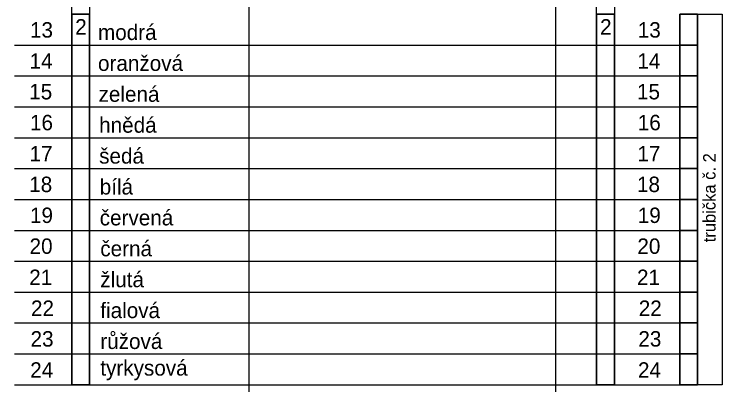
# Model space of a CAD drawing. Extents: x 1901 to 2519, y -3585 to -3154.
# Drawn here: x 2032.8 to 2113, y -3287.5 to -3245.2 of the extents above; entities that cross this region are included whole.
import ezdxf

# ---------------------------------------------------------------- set-up
doc = ezdxf.new("R2010")
doc.units = 0
doc.layers.add('rozvláknění', color=7, linetype='Continuous')

msp = doc.modelspace()

# ---------------------------------------------------------------- linework, layer by layer
at = {"layer": 'rozvláknění'}
for p, q in [((2032.823, -3248.764), (2108.565, -3248.767)), ((2032.823, -3252.283), (2108.565, -3252.285)), ((2032.823, -3255.801), (2108.565, -3255.803)), ((2032.823, -3259.319), (2108.565, -3259.321)), ((2032.823, -3262.837), (2108.565, -3262.839)), ((2032.823, -3266.355), (2108.565, -3266.357)), ((2032.823, -3269.874), (2108.565, -3269.876)), ((2032.823, -3273.392), (2108.565, -3273.394)), ((2032.823, -3276.91), (2108.565, -3276.912)), ((2032.823, -3280.428), (2108.565, -3280.43)), ((2032.823, -3283.946), (2108.565, -3283.948)), ((2032.823, -3287.465), (2108.565, -3287.467))]:
    msp.add_line(p, q, dxfattribs=at)
for points in [[(2014.869, -3178.545), (2059.522, -3178.544), (2059.522, -3570.656), (2014.869, -3570.656)], [(2094.462, -3178.545), (2128.46, -3178.544), (2128.46, -3571.465), (2094.462, -3571.465)], [(2041.391, -3287.481), (2039.35, -3287.481), (2039.35, -3203.008), (2041.391, -3203.008)], [(2101.143, -3287.481), (2099.102, -3287.481), (2099.102, -3203.008), (2101.143, -3203.008)], [(2041.391, -3287.467), (2039.35, -3287.467), (2039.35, -3245.248), (2041.391, -3245.248)], [(2101.143, -3287.467), (2099.102, -3287.467), (2099.102, -3245.248), (2101.143, -3245.248)], [(2108.565, -3245.248), (2110.606, -3245.248), (2110.606, -3248.767), (2108.565, -3248.767)], [(2108.565, -3245.248), (2110.606, -3245.248), (2110.606, -3248.767), (2108.565, -3248.767)], [(2110.606, -3245.248), (2113.393, -3245.248), (2113.393, -3287.463), (2110.606, -3287.463)], [(2108.565, -3248.767), (2110.606, -3248.767), (2110.606, -3252.285), (2108.565, -3252.285)], [(2108.565, -3248.767), (2110.606, -3248.767), (2110.606, -3252.285), (2108.565, -3252.285)], [(2108.565, -3252.285), (2110.606, -3252.285), (2110.606, -3255.803), (2108.565, -3255.803)], [(2108.565, -3252.285), (2110.606, -3252.285), (2110.606, -3255.803), (2108.565, -3255.803)], [(2108.565, -3255.803), (2110.606, -3255.803), (2110.606, -3259.321), (2108.565, -3259.321)], [(2108.565, -3255.803), (2110.606, -3255.803), (2110.606, -3259.321), (2108.565, -3259.321)], [(2108.565, -3259.321), (2110.606, -3259.321), (2110.606, -3262.839), (2108.565, -3262.839)], [(2108.565, -3259.321), (2110.606, -3259.321), (2110.606, -3262.839), (2108.565, -3262.839)], [(2108.565, -3262.839), (2110.606, -3262.839), (2110.606, -3266.357), (2108.565, -3266.357)], [(2108.565, -3262.839), (2110.606, -3262.839), (2110.606, -3266.357), (2108.565, -3266.357)], [(2108.565, -3266.357), (2110.606, -3266.357), (2110.606, -3269.876), (2108.565, -3269.876)], [(2108.565, -3266.357), (2110.606, -3266.357), (2110.606, -3269.876), (2108.565, -3269.876)], [(2108.565, -3269.876), (2110.606, -3269.876), (2110.606, -3273.394), (2108.565, -3273.394)], [(2108.565, -3269.876), (2110.606, -3269.876), (2110.606, -3273.394), (2108.565, -3273.394)], [(2108.565, -3273.394), (2110.606, -3273.394), (2110.606, -3276.912), (2108.565, -3276.912)], [(2108.565, -3273.394), (2110.606, -3273.394), (2110.606, -3276.912), (2108.565, -3276.912)], [(2108.565, -3276.912), (2110.606, -3276.912), (2110.606, -3280.43), (2108.565, -3280.43)], [(2108.565, -3276.912), (2110.606, -3276.912), (2110.606, -3280.43), (2108.565, -3280.43)], [(2108.565, -3280.43), (2110.606, -3280.43), (2110.606, -3283.948), (2108.565, -3283.948)], [(2108.565, -3280.43), (2110.606, -3280.43), (2110.606, -3283.948), (2108.565, -3283.948)], [(2108.565, -3283.948), (2110.606, -3283.948), (2110.606, -3287.467), (2108.565, -3287.467)], [(2108.565, -3283.948), (2110.606, -3283.948), (2110.606, -3287.467), (2108.565, -3287.467)]]:
    msp.add_lwpolyline(points, close=True, dxfattribs=at)
for points in [[(2041.391, -3245.248), (2039.35, -3245.248), (2039.35, -3287.467), (2041.391, -3287.467), (2041.391, -3245.248)], [(2041.391, -3245.248), (2039.35, -3245.248), (2039.35, -3287.467), (2041.391, -3287.467), (2041.391, -3245.248)], [(2041.391, -3245.248), (2039.35, -3245.248), (2039.35, -3287.467), (2041.391, -3287.467), (2041.391, -3245.248)], [(2041.391, -3245.248), (2039.35, -3245.248), (2039.35, -3287.467), (2041.391, -3287.467), (2041.391, -3245.248)], [(2041.391, -3245.248), (2039.35, -3245.248), (2039.35, -3287.467), (2041.391, -3287.467), (2041.391, -3245.248)], [(2041.391, -3245.248), (2039.35, -3245.248), (2039.35, -3287.467), (2041.391, -3287.467), (2041.391, -3245.248)], [(2101.143, -3245.248), (2099.102, -3245.248), (2099.102, -3287.467), (2101.143, -3287.467), (2101.143, -3245.248)], [(2101.143, -3245.248), (2099.102, -3245.248), (2099.102, -3287.467), (2101.143, -3287.467), (2101.143, -3245.248)], [(2101.143, -3245.248), (2099.102, -3245.248), (2099.102, -3287.467), (2101.143, -3287.467), (2101.143, -3245.248)], [(2101.143, -3245.248), (2099.102, -3245.248), (2099.102, -3287.467), (2101.143, -3287.467), (2101.143, -3245.248)], [(2101.143, -3245.248), (2099.102, -3245.248), (2099.102, -3287.467), (2101.143, -3287.467), (2101.143, -3245.248)], [(2101.143, -3245.248), (2099.102, -3245.248), (2099.102, -3287.467), (2101.143, -3287.467), (2101.143, -3245.248)], [(2108.565, -3248.767), (2110.606, -3248.767), (2110.606, -3245.248), (2108.565, -3245.248), (2108.565, -3248.767)], [(2108.565, -3248.767), (2110.606, -3248.767), (2110.606, -3245.248), (2108.565, -3245.248), (2108.565, -3248.767)], [(2108.565, -3248.767), (2110.606, -3248.767), (2110.606, -3245.248), (2108.565, -3245.248), (2108.565, -3248.767)], [(2108.565, -3248.767), (2110.606, -3248.767), (2110.606, -3245.248), (2108.565, -3245.248), (2108.565, -3248.767)], [(2108.565, -3248.767), (2110.606, -3248.767), (2110.606, -3245.248), (2108.565, -3245.248), (2108.565, -3248.767)], [(2108.565, -3248.767), (2110.606, -3248.767), (2110.606, -3245.248), (2108.565, -3245.248), (2108.565, -3248.767)], [(2108.565, -3248.767), (2110.606, -3248.767), (2110.606, -3245.248), (2108.565, -3245.248), (2108.565, -3248.767)], [(2108.565, -3248.767), (2110.606, -3248.767), (2110.606, -3245.248), (2108.565, -3245.248), (2108.565, -3248.767)], [(2108.565, -3248.767), (2110.606, -3248.767), (2110.606, -3245.248), (2108.565, -3245.248), (2108.565, -3248.767)], [(2108.565, -3248.767), (2110.606, -3248.767), (2110.606, -3245.248), (2108.565, -3245.248), (2108.565, -3248.767)], [(2108.565, -3248.764), (2108.565, -3283.964)], [(2108.565, -3252.285), (2110.606, -3252.285), (2110.606, -3248.767), (2108.565, -3248.767), (2108.565, -3252.285)], [(2108.565, -3252.285), (2110.606, -3252.285), (2110.606, -3248.767), (2108.565, -3248.767), (2108.565, -3252.285)], [(2108.565, -3252.285), (2110.606, -3252.285), (2110.606, -3248.767), (2108.565, -3248.767), (2108.565, -3252.285)], [(2108.565, -3252.285), (2110.606, -3252.285), (2110.606, -3248.767), (2108.565, -3248.767), (2108.565, -3252.285)], [(2108.565, -3252.285), (2110.606, -3252.285), (2110.606, -3248.767), (2108.565, -3248.767), (2108.565, -3252.285)], [(2108.565, -3252.285), (2110.606, -3252.285), (2110.606, -3248.767), (2108.565, -3248.767), (2108.565, -3252.285)], [(2108.565, -3252.285), (2110.606, -3252.285), (2110.606, -3248.767), (2108.565, -3248.767), (2108.565, -3252.285)], [(2108.565, -3252.285), (2110.606, -3252.285), (2110.606, -3248.767), (2108.565, -3248.767), (2108.565, -3252.285)], [(2108.565, -3252.285), (2110.606, -3252.285), (2110.606, -3248.767), (2108.565, -3248.767), (2108.565, -3252.285)], [(2108.565, -3252.285), (2110.606, -3252.285), (2110.606, -3248.767), (2108.565, -3248.767), (2108.565, -3252.285)], [(2108.565, -3255.803), (2110.606, -3255.803), (2110.606, -3252.285), (2108.565, -3252.285), (2108.565, -3255.803)], [(2108.565, -3255.803), (2110.606, -3255.803), (2110.606, -3252.285), (2108.565, -3252.285), (2108.565, -3255.803)], [(2108.565, -3255.803), (2110.606, -3255.803), (2110.606, -3252.285), (2108.565, -3252.285), (2108.565, -3255.803)], [(2108.565, -3255.803), (2110.606, -3255.803), (2110.606, -3252.285), (2108.565, -3252.285), (2108.565, -3255.803)], [(2108.565, -3255.803), (2110.606, -3255.803), (2110.606, -3252.285), (2108.565, -3252.285), (2108.565, -3255.803)], [(2108.565, -3255.803), (2110.606, -3255.803), (2110.606, -3252.285), (2108.565, -3252.285), (2108.565, -3255.803)], [(2108.565, -3255.803), (2110.606, -3255.803), (2110.606, -3252.285), (2108.565, -3252.285), (2108.565, -3255.803)], [(2108.565, -3255.803), (2110.606, -3255.803), (2110.606, -3252.285), (2108.565, -3252.285), (2108.565, -3255.803)], [(2108.565, -3255.803), (2110.606, -3255.803), (2110.606, -3252.285), (2108.565, -3252.285), (2108.565, -3255.803)], [(2108.565, -3255.803), (2110.606, -3255.803), (2110.606, -3252.285), (2108.565, -3252.285), (2108.565, -3255.803)], [(2108.565, -3259.321), (2110.606, -3259.321), (2110.606, -3255.803), (2108.565, -3255.803), (2108.565, -3259.321)], [(2108.565, -3259.321), (2110.606, -3259.321), (2110.606, -3255.803), (2108.565, -3255.803), (2108.565, -3259.321)], [(2108.565, -3259.321), (2110.606, -3259.321), (2110.606, -3255.803), (2108.565, -3255.803), (2108.565, -3259.321)], [(2108.565, -3259.321), (2110.606, -3259.321), (2110.606, -3255.803), (2108.565, -3255.803), (2108.565, -3259.321)], [(2108.565, -3259.321), (2110.606, -3259.321), (2110.606, -3255.803), (2108.565, -3255.803), (2108.565, -3259.321)], [(2108.565, -3259.321), (2110.606, -3259.321), (2110.606, -3255.803), (2108.565, -3255.803), (2108.565, -3259.321)], [(2108.565, -3259.321), (2110.606, -3259.321), (2110.606, -3255.803), (2108.565, -3255.803), (2108.565, -3259.321)], [(2108.565, -3259.321), (2110.606, -3259.321), (2110.606, -3255.803), (2108.565, -3255.803), (2108.565, -3259.321)], [(2108.565, -3259.321), (2110.606, -3259.321), (2110.606, -3255.803), (2108.565, -3255.803), (2108.565, -3259.321)], [(2108.565, -3259.321), (2110.606, -3259.321), (2110.606, -3255.803), (2108.565, -3255.803), (2108.565, -3259.321)], [(2108.565, -3262.839), (2110.606, -3262.839), (2110.606, -3259.321), (2108.565, -3259.321), (2108.565, -3262.839)], [(2108.565, -3262.839), (2110.606, -3262.839), (2110.606, -3259.321), (2108.565, -3259.321), (2108.565, -3262.839)], [(2108.565, -3262.839), (2110.606, -3262.839), (2110.606, -3259.321), (2108.565, -3259.321), (2108.565, -3262.839)], [(2108.565, -3262.839), (2110.606, -3262.839), (2110.606, -3259.321), (2108.565, -3259.321), (2108.565, -3262.839)], [(2108.565, -3262.839), (2110.606, -3262.839), (2110.606, -3259.321), (2108.565, -3259.321), (2108.565, -3262.839)], [(2108.565, -3262.839), (2110.606, -3262.839), (2110.606, -3259.321), (2108.565, -3259.321), (2108.565, -3262.839)], [(2108.565, -3262.839), (2110.606, -3262.839), (2110.606, -3259.321), (2108.565, -3259.321), (2108.565, -3262.839)], [(2108.565, -3262.839), (2110.606, -3262.839), (2110.606, -3259.321), (2108.565, -3259.321), (2108.565, -3262.839)], [(2108.565, -3262.839), (2110.606, -3262.839), (2110.606, -3259.321), (2108.565, -3259.321), (2108.565, -3262.839)], [(2108.565, -3262.839), (2110.606, -3262.839), (2110.606, -3259.321), (2108.565, -3259.321), (2108.565, -3262.839)], [(2108.565, -3266.357), (2110.606, -3266.357), (2110.606, -3262.839), (2108.565, -3262.839), (2108.565, -3266.357)], [(2108.565, -3266.357), (2110.606, -3266.357), (2110.606, -3262.839), (2108.565, -3262.839), (2108.565, -3266.357)], [(2108.565, -3266.357), (2110.606, -3266.357), (2110.606, -3262.839), (2108.565, -3262.839), (2108.565, -3266.357)], [(2108.565, -3266.357), (2110.606, -3266.357), (2110.606, -3262.839), (2108.565, -3262.839), (2108.565, -3266.357)], [(2108.565, -3266.357), (2110.606, -3266.357), (2110.606, -3262.839), (2108.565, -3262.839), (2108.565, -3266.357)], [(2108.565, -3266.357), (2110.606, -3266.357), (2110.606, -3262.839), (2108.565, -3262.839), (2108.565, -3266.357)], [(2108.565, -3266.357), (2110.606, -3266.357), (2110.606, -3262.839), (2108.565, -3262.839), (2108.565, -3266.357)], [(2108.565, -3266.357), (2110.606, -3266.357), (2110.606, -3262.839), (2108.565, -3262.839), (2108.565, -3266.357)], [(2108.565, -3266.357), (2110.606, -3266.357), (2110.606, -3262.839), (2108.565, -3262.839), (2108.565, -3266.357)], [(2108.565, -3266.357), (2110.606, -3266.357), (2110.606, -3262.839), (2108.565, -3262.839), (2108.565, -3266.357)], [(2108.565, -3269.876), (2110.606, -3269.876), (2110.606, -3266.357), (2108.565, -3266.357), (2108.565, -3269.876)], [(2108.565, -3269.876), (2110.606, -3269.876), (2110.606, -3266.357), (2108.565, -3266.357), (2108.565, -3269.876)], [(2108.565, -3269.876), (2110.606, -3269.876), (2110.606, -3266.357), (2108.565, -3266.357), (2108.565, -3269.876)], [(2108.565, -3269.876), (2110.606, -3269.876), (2110.606, -3266.357), (2108.565, -3266.357), (2108.565, -3269.876)], [(2108.565, -3269.876), (2110.606, -3269.876), (2110.606, -3266.357), (2108.565, -3266.357), (2108.565, -3269.876)], [(2108.565, -3269.876), (2110.606, -3269.876), (2110.606, -3266.357), (2108.565, -3266.357), (2108.565, -3269.876)], [(2108.565, -3269.876), (2110.606, -3269.876), (2110.606, -3266.357), (2108.565, -3266.357), (2108.565, -3269.876)], [(2108.565, -3269.876), (2110.606, -3269.876), (2110.606, -3266.357), (2108.565, -3266.357), (2108.565, -3269.876)], [(2108.565, -3269.876), (2110.606, -3269.876), (2110.606, -3266.357), (2108.565, -3266.357), (2108.565, -3269.876)], [(2108.565, -3269.876), (2110.606, -3269.876), (2110.606, -3266.357), (2108.565, -3266.357), (2108.565, -3269.876)], [(2108.565, -3273.394), (2110.606, -3273.394), (2110.606, -3269.876), (2108.565, -3269.876), (2108.565, -3273.394)], [(2108.565, -3273.394), (2110.606, -3273.394), (2110.606, -3269.876), (2108.565, -3269.876), (2108.565, -3273.394)], [(2108.565, -3273.394), (2110.606, -3273.394), (2110.606, -3269.876), (2108.565, -3269.876), (2108.565, -3273.394)], [(2108.565, -3273.394), (2110.606, -3273.394), (2110.606, -3269.876), (2108.565, -3269.876), (2108.565, -3273.394)], [(2108.565, -3273.394), (2110.606, -3273.394), (2110.606, -3269.876), (2108.565, -3269.876), (2108.565, -3273.394)], [(2108.565, -3273.394), (2110.606, -3273.394), (2110.606, -3269.876), (2108.565, -3269.876), (2108.565, -3273.394)], [(2108.565, -3273.394), (2110.606, -3273.394), (2110.606, -3269.876), (2108.565, -3269.876), (2108.565, -3273.394)], [(2108.565, -3273.394), (2110.606, -3273.394), (2110.606, -3269.876), (2108.565, -3269.876), (2108.565, -3273.394)], [(2108.565, -3273.394), (2110.606, -3273.394), (2110.606, -3269.876), (2108.565, -3269.876), (2108.565, -3273.394)], [(2108.565, -3273.394), (2110.606, -3273.394), (2110.606, -3269.876), (2108.565, -3269.876), (2108.565, -3273.394)], [(2108.565, -3276.912), (2110.606, -3276.912), (2110.606, -3273.394), (2108.565, -3273.394), (2108.565, -3276.912)], [(2108.565, -3276.912), (2110.606, -3276.912), (2110.606, -3273.394), (2108.565, -3273.394), (2108.565, -3276.912)], [(2108.565, -3276.912), (2110.606, -3276.912), (2110.606, -3273.394), (2108.565, -3273.394), (2108.565, -3276.912)], [(2108.565, -3276.912), (2110.606, -3276.912), (2110.606, -3273.394), (2108.565, -3273.394), (2108.565, -3276.912)], [(2108.565, -3276.912), (2110.606, -3276.912), (2110.606, -3273.394), (2108.565, -3273.394), (2108.565, -3276.912)], [(2108.565, -3276.912), (2110.606, -3276.912), (2110.606, -3273.394), (2108.565, -3273.394), (2108.565, -3276.912)], [(2108.565, -3276.912), (2110.606, -3276.912), (2110.606, -3273.394), (2108.565, -3273.394), (2108.565, -3276.912)], [(2108.565, -3276.912), (2110.606, -3276.912), (2110.606, -3273.394), (2108.565, -3273.394), (2108.565, -3276.912)], [(2108.565, -3276.912), (2110.606, -3276.912), (2110.606, -3273.394), (2108.565, -3273.394), (2108.565, -3276.912)], [(2108.565, -3276.912), (2110.606, -3276.912), (2110.606, -3273.394), (2108.565, -3273.394), (2108.565, -3276.912)], [(2108.565, -3280.43), (2110.606, -3280.43), (2110.606, -3276.912), (2108.565, -3276.912), (2108.565, -3280.43)], [(2108.565, -3280.43), (2110.606, -3280.43), (2110.606, -3276.912), (2108.565, -3276.912), (2108.565, -3280.43)], [(2108.565, -3280.43), (2110.606, -3280.43), (2110.606, -3276.912), (2108.565, -3276.912), (2108.565, -3280.43)], [(2108.565, -3280.43), (2110.606, -3280.43), (2110.606, -3276.912), (2108.565, -3276.912), (2108.565, -3280.43)], [(2108.565, -3280.43), (2110.606, -3280.43), (2110.606, -3276.912), (2108.565, -3276.912), (2108.565, -3280.43)], [(2108.565, -3280.43), (2110.606, -3280.43), (2110.606, -3276.912), (2108.565, -3276.912), (2108.565, -3280.43)], [(2108.565, -3280.43), (2110.606, -3280.43), (2110.606, -3276.912), (2108.565, -3276.912), (2108.565, -3280.43)], [(2108.565, -3280.43), (2110.606, -3280.43), (2110.606, -3276.912), (2108.565, -3276.912), (2108.565, -3280.43)], [(2108.565, -3280.43), (2110.606, -3280.43), (2110.606, -3276.912), (2108.565, -3276.912), (2108.565, -3280.43)], [(2108.565, -3280.43), (2110.606, -3280.43), (2110.606, -3276.912), (2108.565, -3276.912), (2108.565, -3280.43)], [(2108.565, -3283.948), (2110.606, -3283.948), (2110.606, -3280.43), (2108.565, -3280.43), (2108.565, -3283.948)], [(2108.565, -3283.948), (2110.606, -3283.948), (2110.606, -3280.43), (2108.565, -3280.43), (2108.565, -3283.948)], [(2108.565, -3283.948), (2110.606, -3283.948), (2110.606, -3280.43), (2108.565, -3280.43), (2108.565, -3283.948)], [(2108.565, -3283.948), (2110.606, -3283.948), (2110.606, -3280.43), (2108.565, -3280.43), (2108.565, -3283.948)], [(2108.565, -3283.948), (2110.606, -3283.948), (2110.606, -3280.43), (2108.565, -3280.43), (2108.565, -3283.948)], [(2108.565, -3283.948), (2110.606, -3283.948), (2110.606, -3280.43), (2108.565, -3280.43), (2108.565, -3283.948)], [(2108.565, -3283.948), (2110.606, -3283.948), (2110.606, -3280.43), (2108.565, -3280.43), (2108.565, -3283.948)], [(2108.565, -3283.948), (2110.606, -3283.948), (2110.606, -3280.43), (2108.565, -3280.43), (2108.565, -3283.948)], [(2108.565, -3283.948), (2110.606, -3283.948), (2110.606, -3280.43), (2108.565, -3280.43), (2108.565, -3283.948)], [(2108.565, -3283.948), (2110.606, -3283.948), (2110.606, -3280.43), (2108.565, -3280.43), (2108.565, -3283.948)], [(2108.565, -3287.467), (2110.606, -3287.467), (2110.606, -3283.948), (2108.565, -3283.948), (2108.565, -3287.467)], [(2108.565, -3287.467), (2110.606, -3287.467), (2110.606, -3283.948), (2108.565, -3283.948), (2108.565, -3287.467)], [(2108.565, -3287.467), (2110.606, -3287.467), (2110.606, -3283.948), (2108.565, -3283.948), (2108.565, -3287.467)], [(2108.565, -3287.467), (2110.606, -3287.467), (2110.606, -3283.948), (2108.565, -3283.948), (2108.565, -3287.467)], [(2108.565, -3287.467), (2110.606, -3287.467), (2110.606, -3283.948), (2108.565, -3283.948), (2108.565, -3287.467)], [(2108.565, -3287.467), (2110.606, -3287.467), (2110.606, -3283.948), (2108.565, -3283.948), (2108.565, -3287.467)], [(2108.565, -3287.467), (2110.606, -3287.467), (2110.606, -3283.948), (2108.565, -3283.948), (2108.565, -3287.467)], [(2108.565, -3287.467), (2110.606, -3287.467), (2110.606, -3283.948), (2108.565, -3283.948), (2108.565, -3287.467)], [(2108.565, -3287.467), (2110.606, -3287.467), (2110.606, -3283.948), (2108.565, -3283.948), (2108.565, -3287.467)], [(2108.565, -3287.467), (2110.606, -3287.467), (2110.606, -3283.948), (2108.565, -3283.948), (2108.565, -3287.467)]]:
    msp.add_lwpolyline(points, dxfattribs=at)

# ---------------------------------------------------------------- texts
for s, p in [('13', (2034.604, -3247.917)), ('2', (2039.749, -3247.574)), ('2', (2039.749, -3247.574)), ('2', (2099.501, -3247.574)), ('2', (2099.501, -3247.574)), ('13', (2103.793, -3247.917)), ('modrá', (2042.346, -3248.193)), ('14', (2034.557, -3251.466)), ('oranžová', (2042.346, -3251.713)), ('14', (2103.746, -3251.466)), ('15', (2034.515, -3254.957)), ('zelená', (2042.411, -3255.233)), ('15', (2103.704, -3254.957)), ('16', (2034.604, -3258.477)), ('hnědá', (2042.477, -3258.753)), ('16', (2103.793, -3258.477)), ('17', (2034.557, -3262.026)), ('šedá', (2042.477, -3262.273)), ('17', (2103.746, -3262.026)), ('18', (2034.515, -3265.517)), ('18', (2103.704, -3265.517)), ('bílá', (2042.542, -3265.793)), ('19', (2034.604, -3269.037)), ('červená', (2042.542, -3269.313)), ('19', (2103.793, -3269.037)), ('20', (2034.557, -3272.557)), ('černá', (2042.608, -3272.833)), ('20', (2103.746, -3272.557)), ('21', (2034.515, -3276.106)), ('žlutá', (2042.608, -3276.353)), ('21', (2103.704, -3276.106)), ('22', (2034.717, -3279.626)), ('fialová', (2042.608, -3279.873)), ('22', (2103.906, -3279.626)), ('23', (2034.67, -3283.117)), ('růžová', (2042.608, -3283.393)), ('23', (2103.86, -3283.117)), ('tyrkysová', (2042.608, -3286.425)), ('24', (2034.628, -3286.666)), ('24', (2103.817, -3286.666))]:
    msp.add_text(s, height=1.76, dxfattribs=at).set_placement(p)
msp.add_text('trubička č. 2', height=1.408, rotation=90, dxfattribs=at).set_placement((2112.642, -3271.237))

doc.saveas('drawing.dxf')
